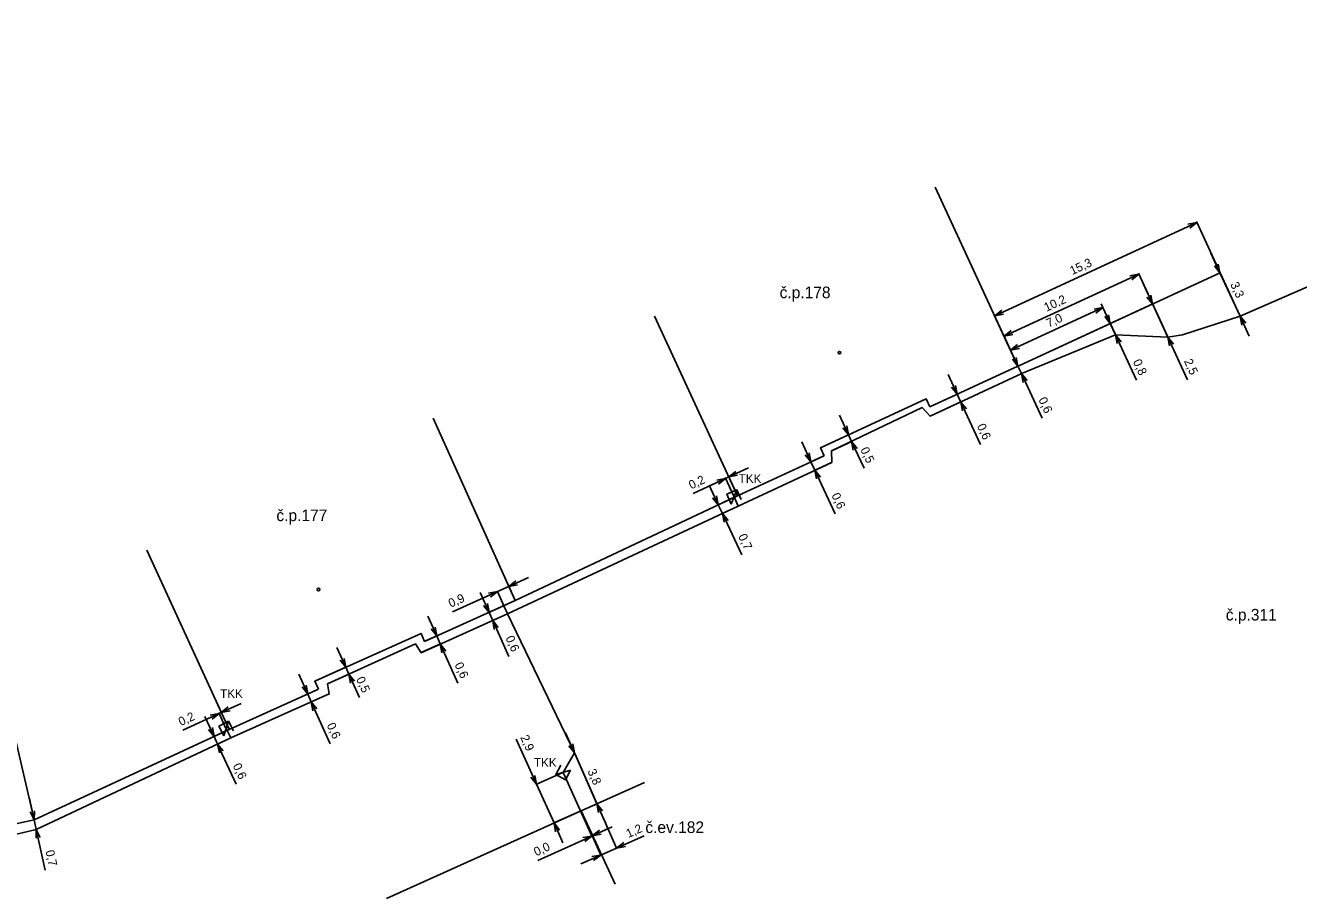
# Model space of a CAD drawing. Extents: x -770877 to -770229, y -1050342 to -1050226.
# Drawn here: x -770384.5 to -770296.8, y -1050312.2 to -1050252.1 of the extents above; entities that cross this region are included whole.
import ezdxf

# ---------------------------------------------------------------- set-up
doc = ezdxf.new("R2010")
doc.units = 0
for name, color, linetype in [('f001_pol_linie', 7, 'Continuous'), ('f001_pol_znacky', 7, 'Continuous'), ('f003_opt_sit_texty', 7, 'Continuous'), ('f003_opt_sit_znacky', 7, 'Continuous'), ('f006_osa_trasy', 7, 'Continuous'), ('f006_stp_koty', 7, 'Continuous'), ('Inspire adresy', 7, 'Continuous')]:
    doc.layers.add(name, color=color, linetype=linetype)

msp = doc.modelspace()

# ---------------------------------------------------------------- linework, layer by layer
at = {"layer": 'f001_pol_linie'}
for points in [[(-770322.19, -1050278.36), (-770316.11, -1050275.55), (-770321.81, -1050263.2)], [(-770341.17, -1050272.09), (-770335.45, -1050284.48), (-770329.48, -1050281.72)], [(-770329.48, -1050281.72), (-770329.73, -1050281.18), (-770322.45, -1050277.79), (-770322.19, -1050278.36)], [(-770357.01, -1050294.52), (-770350.77, -1050291.71), (-770356.43, -1050279.14)], [(-770350.77, -1050291.71), (-770335.45, -1050284.48)], [(-770376.17, -1050288.23), (-770370.49, -1050300.59), (-770364.33, -1050297.82)], [(-770364.33, -1050297.82), (-770364.58, -1050297.27), (-770357.26, -1050293.97), (-770357.01, -1050294.52)], [(-770405.45, -1050302.49), (-770403.58, -1050311.09), (-770383.92, -1050306.82), (-770385.97, -1050297.98)], [(-770383.92, -1050306.82), (-770370.49, -1050300.59)], [(-770341.86, -1050304.26), (-770346.23, -1050306.2)], [(-770343.87, -1050311.26), (-770346.23, -1050306.2), (-770359.63, -1050312.25)]]:
    msp.add_lwpolyline(points, dxfattribs=at)
at = {"layer": 'f001_pol_znacky'}
for centre in [(-770328.409, -1050274.622), (-770364.329, -1050290.949)]:
    msp.add_circle(centre, 0.0875, dxfattribs=at)
at = {"layer": 'f003_opt_sit_znacky'}
for p, q in [((-770335.871, -1050285.055), (-770335.489, -1050284.065)), ((-770370.86, -1050301.036), (-770370.54, -1050300.024)), ((-770346.964, -1050303.39), (-770347.976, -1050303.71))]:
    msp.add_line(p, q, dxfattribs=at)
for points in [[(-770335.185, -1050284.751), (-770335.489, -1050284.065), (-770336.175, -1050284.369), (-770335.871, -1050285.055)], [(-770370.194, -1050300.69), (-770370.54, -1050300.024), (-770371.206, -1050300.37), (-770370.86, -1050301.036)], [(-770347.63, -1050303.044), (-770347.976, -1050303.71), (-770347.31, -1050304.056), (-770346.964, -1050303.39)]]:
    msp.add_lwpolyline(points, dxfattribs=at)
at = {"layer": 'f006_osa_trasy'}
for points in [[(-770315.81, -1050276.03), (-770309.39, -1050273.38), (-770305.78, -1050273.54), (-770304.76, -1050273.38), (-770300.8, -1050272.11), (-770294, -1050269.13), (-770270.2, -1050258.28), (-770267.99, -1050256.04), (-770266.3, -1050254.86), (-770266.07, -1050254.38), (-770266.31, -1050252.06)], [(-770351.3, -1050292.63), (-770335.39, -1050285.19), (-770328.95, -1050282.18), (-770328.96, -1050281.38), (-770322.72, -1050278.4), (-770322.17, -1050279), (-770315.81, -1050276.03)], [(-770335.39, -1050285.19), (-770335.68, -1050284.56)], [(-770370.36, -1050301.17), (-770363.59, -1050298.14), (-770363.71, -1050297.45), (-770357.65, -1050294.7), (-770357.26, -1050295.3), (-770351.3, -1050292.63), (-770346.69, -1050302.2), (-770347.47, -1050303.55)], [(-770370.36, -1050301.17), (-770370.7, -1050300.53)], [(-770395, -1050310.16), (-770383.78, -1050307.48), (-770370.36, -1050301.17)]]:
    msp.add_lwpolyline(points, dxfattribs=at)
at = {"layer": 'f006_stp_koty'}
for p, q in [((-770317.715, -1050272.076), (-770303.79, -1050265.641)), ((-770300.825, -1050272.056), (-770303.815, -1050265.586)), ((-770302.814, -1050267.752), (-770302.185, -1050269.114)), ((-770317.064, -1050273.486), (-770307.787, -1050269.198)), ((-770316.056, -1050275.525), (-770302.13, -1050269.089)), ((-770305.805, -1050273.486), (-770307.812, -1050269.144)), ((-770300.8, -1050272.11), (-770302.185, -1050269.114)), ((-770307.462, -1050269.901), (-770306.833, -1050271.262)), ((-770316.622, -1050274.443), (-770310.258, -1050271.502)), ((-770316.056, -1050275.525), (-770306.778, -1050271.237)), ((-770310.376, -1050271.247), (-770309.746, -1050272.609)), ((-770309.415, -1050273.326), (-770310.283, -1050271.447)), ((-770305.78, -1050273.54), (-770306.833, -1050271.262)), ((-770316.135, -1050275.496), (-770317.741, -1050272.022)), ((-770316.056, -1050275.525), (-770309.692, -1050272.584)), ((-770309.39, -1050273.38), (-770309.746, -1050272.609)), ((-770300.171, -1050273.472), (-770300.8, -1050272.11)), ((-770316.135, -1050275.496), (-770317.089, -1050273.431)), ((-770307.94, -1050276.517), (-770309.39, -1050273.38)), ((-770304.418, -1050276.487), (-770305.78, -1050273.54)), ((-770316.739, -1050274.188), (-770316.11, -1050275.55)), ((-770316.135, -1050275.496), (-770316.647, -1050274.388)), ((-770320.924, -1050276.123), (-770320.295, -1050277.484)), ((-770315.874, -1050276.06), (-770316.11, -1050275.55)), ((-770315.864, -1050276.055), (-770315.929, -1050276.085)), ((-770314.453, -1050279.135), (-770315.874, -1050276.06)), ((-770322.136, -1050278.335), (-770320.241, -1050277.459)), ((-770322.116, -1050278.975), (-770319.993, -1050277.994)), ((-770320.048, -1050278.019), (-770320.295, -1050277.484)), ((-770318.69, -1050280.957), (-770320.048, -1050278.019)), ((-770328.424, -1050278.917), (-770327.791, -1050280.277)), ((-770329.676, -1050281.155), (-770327.737, -1050280.252)), ((-770327.577, -1050280.736), (-770327.791, -1050280.277)), ((-770331.012, -1050280.776), (-770330.382, -1050282.137)), ((-770328.906, -1050281.355), (-770327.523, -1050280.711)), ((-770326.722, -1050282.573), (-770327.577, -1050280.736)), ((-770329.534, -1050281.745), (-770330.437, -1050282.162)), ((-770330.114, -1050282.718), (-770330.382, -1050282.137)), ((-770329.004, -1050282.205), (-770330.168, -1050282.743)), ((-770338.507, -1050284.324), (-770336.266, -1050283.29)), ((-770335.705, -1050284.506), (-770336.292, -1050283.235)), ((-770336.266, -1050283.29), (-770336.046, -1050283.188)), ((-770335.475, -1050284.426), (-770336.072, -1050283.134)), ((-770334.685, -1050282.559), (-770336.046, -1050283.188)), ((-770328.72, -1050285.733), (-770330.114, -1050282.718)), ((-770337.407, -1050283.745), (-770336.767, -1050285.101)), ((-770335.504, -1050284.506), (-770336.821, -1050285.127)), ((-770336.482, -1050285.705), (-770336.767, -1050285.101)), ((-770335.444, -1050285.216), (-770336.536, -1050285.731)), ((-770335.139, -1050288.551), (-770336.482, -1050285.705)), ((-770349.842, -1050290.118), (-770351.21, -1050290.734)), ((-770355.084, -1050292.478), (-770351.995, -1050291.087)), ((-770353.189, -1050291.154), (-770352.573, -1050292.522)), ((-770351.325, -1050292.575), (-770352.019, -1050291.033)), ((-770351.21, -1050290.734), (-770351.995, -1050291.087)), ((-770350.795, -1050291.655), (-770351.234, -1050290.679)), ((-770350.825, -1050291.735), (-770352.628, -1050292.547)), ((-770356.796, -1050292.778), (-770356.18, -1050294.146)), ((-770352.318, -1050293.089), (-770352.573, -1050292.522)), ((-770351.355, -1050292.655), (-770352.373, -1050293.113)), ((-770351.199, -1050295.573), (-770352.318, -1050293.089)), ((-770357.205, -1050295.275), (-770355.875, -1050294.676)), ((-770356.955, -1050294.495), (-770356.125, -1050294.122)), ((-770355.93, -1050294.701), (-770356.18, -1050294.146)), ((-770354.711, -1050297.409), (-770355.93, -1050294.701)), ((-770363.059, -1050294.939), (-770362.443, -1050296.307)), ((-770364.525, -1050297.245), (-770362.388, -1050296.282)), ((-770362.229, -1050296.782), (-770362.443, -1050296.307)), ((-770365.68, -1050296.783), (-770365.065, -1050298.151)), ((-770363.655, -1050297.425), (-770362.174, -1050296.757)), ((-770361.499, -1050298.399), (-770362.229, -1050296.782)), ((-770364.385, -1050297.845), (-770365.12, -1050298.175)), ((-770364.821, -1050298.694), (-770365.065, -1050298.151)), ((-770363.645, -1050298.165), (-770364.876, -1050298.718)), ((-770369.665, -1050298.793), (-770371.028, -1050299.419)), ((-770363.524, -1050301.578), (-770364.821, -1050298.694)), ((-770373.685, -1050300.64), (-770371.179, -1050299.489)), ((-770372.153, -1050299.708), (-770371.522, -1050301.069)), ((-770370.725, -1050300.475), (-770371.204, -1050299.434)), ((-770371.179, -1050299.489), (-770371.028, -1050299.419)), ((-770370.515, -1050300.535), (-770371.053, -1050299.365)), ((-770370.544, -1050300.615), (-770371.577, -1050301.094)), ((-770347.299, -1050300.829), (-770346.69, -1050302.2)), ((-770371.278, -1050301.596), (-770371.522, -1050301.069)), ((-770370.414, -1050301.195), (-770371.332, -1050301.621)), ((-770369.991, -1050304.371), (-770371.278, -1050301.596)), ((-770350.703, -1050301.258), (-770349.296, -1050304.374)), ((-770346.69, -1050302.2), (-770345.131, -1050305.712)), ((-770346.666, -1050302.255), (-770343.75, -1050308.823)), ((-770347.525, -1050303.575), (-770349.351, -1050304.399)), ((-770347.445, -1050303.605), (-770345.462, -1050307.997)), ((-770349.296, -1050304.374), (-770348.092, -1050307.041)), ((-770384.238, -1050305.354), (-770383.92, -1050306.82)), ((-770346.175, -1050306.176), (-770345.076, -1050305.688)), ((-770344.522, -1050307.083), (-770345.131, -1050305.712)), ((-770383.777, -1050307.479), (-770383.92, -1050306.82)), ((-770346.285, -1050306.225), (-770348.147, -1050307.065)), ((-770346.206, -1050306.255), (-770344.849, -1050309.311)), ((-770346.205, -1050306.255), (-770345.426, -1050307.981)), ((-770383.167, -1050310.286), (-770383.777, -1050307.479)), ((-770347.475, -1050308.408), (-770348.092, -1050307.041)), ((-770344.084, -1050307.309), (-770345.451, -1050307.926)), ((-770349.196, -1050309.617), (-770345.487, -1050307.942)), ((-770341.866, -1050307.921), (-770343.774, -1050308.769)), ((-770346.244, -1050309.865), (-770344.873, -1050309.257)), ((-770344.873, -1050309.257), (-770343.774, -1050308.769))]:
    msp.add_line(p, q, dxfattribs=at)
for points in [[(-770304.398, -1050265.756), (-770303.79, -1050265.641), (-770304.272, -1050266.028)], [(-770308.394, -1050269.314), (-770307.787, -1050269.198), (-770308.268, -1050269.586)], [(-770302.3, -1050268.507), (-770302.185, -1050269.114), (-770302.573, -1050268.632)], [(-770306.948, -1050270.655), (-770306.833, -1050271.262), (-770307.221, -1050270.781)], [(-770317.108, -1050271.961), (-770317.715, -1050272.076), (-770317.234, -1050271.689)], [(-770310.866, -1050271.617), (-770310.258, -1050271.502), (-770310.74, -1050271.889)], [(-770309.862, -1050272.001), (-770309.746, -1050272.609), (-770310.134, -1050272.127)], [(-770300.684, -1050272.718), (-770300.8, -1050272.11), (-770300.412, -1050272.592)], [(-770316.456, -1050273.37), (-770317.064, -1050273.486), (-770316.582, -1050273.098)], [(-770309.274, -1050273.988), (-770309.39, -1050273.38), (-770309.002, -1050273.862)], [(-770305.664, -1050274.148), (-770305.78, -1050273.54), (-770305.392, -1050274.022)], [(-770316.014, -1050274.327), (-770316.622, -1050274.443), (-770316.14, -1050274.055)], [(-770316.226, -1050274.942), (-770316.11, -1050275.55), (-770316.498, -1050275.068)], [(-770315.759, -1050276.667), (-770315.874, -1050276.06), (-770315.487, -1050276.541)], [(-770320.411, -1050276.877), (-770320.295, -1050277.484), (-770320.683, -1050277.002)], [(-770319.932, -1050278.627), (-770320.048, -1050278.019), (-770319.66, -1050278.501)], [(-770327.908, -1050279.67), (-770327.791, -1050280.277), (-770328.18, -1050279.796)], [(-770330.498, -1050281.53), (-770330.382, -1050282.137), (-770330.77, -1050281.655)], [(-770327.46, -1050281.343), (-770327.577, -1050280.736), (-770327.188, -1050281.217)], [(-770336.874, -1050283.405), (-770336.266, -1050283.29), (-770336.748, -1050283.677)], [(-770335.439, -1050283.073), (-770336.046, -1050283.188), (-770335.565, -1050282.8)], [(-770329.998, -1050283.326), (-770330.114, -1050282.718), (-770329.726, -1050283.2)], [(-770336.887, -1050284.495), (-770336.767, -1050285.101), (-770337.159, -1050284.623)], [(-770336.361, -1050286.312), (-770336.482, -1050285.705), (-770336.09, -1050286.184)], [(-770352.603, -1050291.197), (-770351.995, -1050291.087), (-770352.48, -1050291.47)], [(-770350.601, -1050290.624), (-770351.21, -1050290.734), (-770350.724, -1050290.351)], [(-770352.683, -1050291.913), (-770352.573, -1050292.522), (-770352.957, -1050292.037)], [(-770356.29, -1050293.538), (-770356.18, -1050294.146), (-770356.563, -1050293.661)], [(-770352.209, -1050293.697), (-770352.318, -1050293.089), (-770351.935, -1050293.574)], [(-770355.82, -1050295.31), (-770355.93, -1050294.701), (-770355.547, -1050295.187)], [(-770362.553, -1050295.698), (-770362.443, -1050296.307), (-770362.826, -1050295.821)], [(-770362.119, -1050297.391), (-770362.229, -1050296.782), (-770361.845, -1050297.267)], [(-770365.175, -1050297.542), (-770365.065, -1050298.151), (-770365.448, -1050297.665)], [(-770370.42, -1050299.305), (-770371.028, -1050299.419), (-770370.545, -1050299.033)], [(-770364.712, -1050299.302), (-770364.821, -1050298.694), (-770364.438, -1050299.179)], [(-770371.786, -1050299.603), (-770371.179, -1050299.489), (-770371.661, -1050299.876)], [(-770371.639, -1050300.461), (-770371.522, -1050301.069), (-770371.911, -1050300.588)], [(-770371.161, -1050302.203), (-770371.278, -1050301.596), (-770370.889, -1050302.077)], [(-770346.796, -1050301.591), (-770346.69, -1050302.2), (-770347.071, -1050301.712)], [(-770349.406, -1050303.766), (-770349.296, -1050304.374), (-770349.68, -1050303.889)], [(-770345.025, -1050306.321), (-770345.131, -1050305.712), (-770344.75, -1050306.2)], [(-770383.901, -1050306.202), (-770383.92, -1050306.82), (-770384.194, -1050306.266)], [(-770383.796, -1050308.097), (-770383.777, -1050307.479), (-770383.503, -1050308.034)], [(-770347.982, -1050307.649), (-770348.092, -1050307.041), (-770347.708, -1050307.526)], [(-770344.842, -1050307.816), (-770345.451, -1050307.926), (-770344.966, -1050307.542)], [(-770346.095, -1050308.052), (-770345.487, -1050307.942), (-770345.972, -1050308.326)], [(-770343.165, -1050308.662), (-770343.774, -1050308.769), (-770343.286, -1050308.388)], [(-770345.482, -1050309.363), (-770344.873, -1050309.257), (-770345.361, -1050309.637)]]:
    msp.add_lwpolyline(points, dxfattribs=at)

# ---------------------------------------------------------------- texts
at = {"layer": 'f003_opt_sit_texty'}
for p in [(-770335.359, -1050283.594), (-770371.108, -1050298.421), (-770349.474, -1050303.17)]:
    msp.add_text('TKK', height=0.6, dxfattribs=at).set_placement(p)
at = {"layer": 'f006_stp_koty'}
for s, rotation, p in [('15,3', 24.80501, (-770312.371, -1050269.276)), ('3,3', 294.80501, (-770301.491, -1050269.9)), ('10,2', 24.80501, (-770314.147, -1050271.807)), ('7,0', 24.80501, (-770313.992, -1050272.897)), ('0,8', 294.80501, (-770308.203, -1050275.234)), ('2,5', 294.80501, (-770304.681, -1050275.203)), ('0,6', 294.80501, (-770314.716, -1050277.851)), ('0,6', 294.80501, (-770318.953, -1050279.673)), ('0,5', 294.96948, (-770326.988, -1050281.29)), ('0,2', 24.78101, (-770338.633, -1050284.052)), ('0,6', 294.81165, (-770328.983, -1050284.449)), ('0,7', 295.26413, (-770335.412, -1050287.27)), ('0,9', 24.24302, (-770355.207, -1050292.205)), ('0,6', 294.24302, (-770351.45, -1050294.287)), ('0,6', 294.24302, (-770354.961, -1050296.123)), ('0,5', 294.26679, (-770361.75, -1050297.113)), ('0,2', 24.681, (-770373.81, -1050300.368)), ('0,6', 294.21227, (-770363.773, -1050300.292)), ('2,9', 294.29882, (-770350.43, -1050301.134)), ('0,6', 294.88596, (-770370.255, -1050303.087)), ('3,8', 293.93815, (-770345.8, -1050303.465)), ('1,2', 23.93815, (-770342.967, -1050308.082)), ('0,0', 24.29882, (-770349.319, -1050309.343)), ('0,7', 282.25388, (-770383.145, -1050308.976))]:
    msp.add_text(s, height=0.6, rotation=rotation, dxfattribs=at).set_placement(p)
at = {"layer": 'Inspire adresy'}
for s, p in [('č.p.178', (-770332.539, -1050270.863)), ('č.p.177', (-770367.229, -1050286.233)), ('č.p.311', (-770301.784, -1050293.083)), ('č.ev.182', (-770341.794, -1050307.733))]:
    msp.add_text(s, height=0.8, dxfattribs=at).set_placement(p)

doc.saveas('drawing.dxf')
